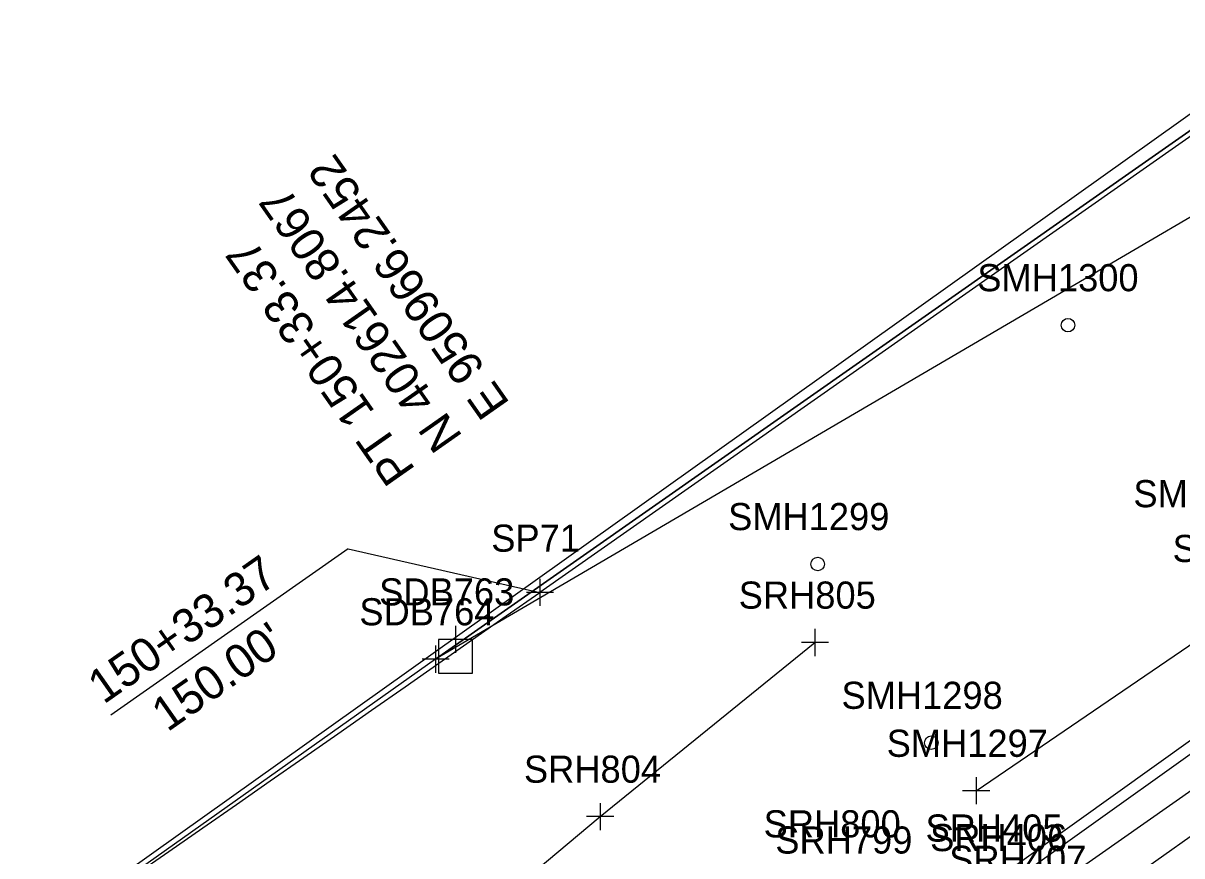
# Model space of a CAD drawing. Extents: x 941041 to 969446, y 397014 to 416764.
# Drawn here: x 950803.9 to 950974.8, y 402698.7 to 402821.6 of the extents above; entities that cross this region are included whole.
import ezdxf

# ---------------------------------------------------------------- set-up
doc = ezdxf.new("R2010")
doc.units = 0
for name, color, linetype in [('SURVEY - CENTERLINE - Preliminary Curve Text', 7, 'Continuous'), ('SURVEY - DRAINAGE - Area Shapes', 7, 'Continuous'), ('SURVEY - DTM - Breaklines', 7, 'Continuous'), ('SURVEY - DTM - Breaklines - Points - Locators', 7, 'Continuous'), ('SURVEY - DTM - Breaklines - Points - Numbers', 7, 'Continuous'), ('SURVEY - DTM - Spot Points - Locators', 7, 'Continuous'), ('SURVEY - DTM - Spot Points - Point Numbers', 7, 'Continuous'), ('SURVEY - DTM GRAPHICS - Boundary Line', 7, 'Continuous'), ('SURVEY - NON-TRANSPORTATION - Features', 7, 'Continuous'), ('SURVEY - NON-TRANSPORTATION - Features - Points - Locators', 7, 'Continuous'), ('SURVEY - NON-TRANSPORTATION - Features - Points - Numbers', 7, 'Continuous'), ('SURVEY - PROPERTY - ROW Lines', 7, 'Continuous'), ('SURVEY - PROPERTY - ROW Lines - Points - Locators', 7, 'Continuous'), ('SURVEY - PROPERTY - ROW Lines - Points - Numbers', 7, 'Continuous'), ('SURVEY - PROPERTY - ROW Markers - Points - Locators', 7, 'Continuous'), ('SURVEY - PROPERTY - ROW Markers - Points - Numbers', 7, 'Continuous'), ('SURVEY - PROPERTY - ROW Markers with Text', 7, 'Continuous'), ('SURVEY - PROPERTY - Station and Offset Flags', 7, 'Continuous'), ('SURVEY - TRANSPORTATION - Features', 7, 'Continuous'), ('SURVEY - TRANSPORTATION - Features - Points - Numbers', 7, 'Continuous'), ('SURVEY - TRANSPORTATION - Roads', 7, 'Continuous'), ('SURVEY - TRANSPORTATION - Roads - Points - Numbers', 7, 'Continuous'), ('SURVEY - VEGETATION - Features with Text', 7, 'Continuous')]:
    doc.layers.add(name, color=color, linetype=linetype)

msp = doc.modelspace()

# ---------------------------------------------------------------- linework, layer by layer
at = {"layer": 'SURVEY - DRAINAGE - Area Shapes'}
for points in [[(951570.1, 403333.86), (951394.91, 403299.54), (951364.56, 403085.05), (950690.3, 402604.57), (950747.14, 402539.76)], [(950765.73, 402528.11), (951145.6, 402792.15), (951242.57, 402873.52), (951348.31, 402952.21), (951398.95, 403004.27), (951428.85, 403040.93), (951473.12, 403113.97), (951570.1, 403333.86), (951394.91, 403299.54), (951364.56, 403085.05), (950690.3, 402604.57), (950747.14, 402539.76), (950765.73, 402528.11)]]:
    msp.add_lwpolyline(points, dxfattribs=at)
at = {"layer": 'SURVEY - DTM - Breaklines'}
for points in [[(951404.5, 403057.02), (951388.59, 403034.18), (951373.81, 403016.3), (951353.68, 402995.42), (951325.73, 402969.82), (951296.63, 402946.16), (951268.96, 402924.9), (951228.2, 402894.58), (951186.77, 402863.94), (951145.14, 402834.63), (951106.17, 402807.78), (951067.06, 402780.74), (951027.03, 402752.5), (950987.44, 402723.92), (950948.21, 402695.85), (950901.61, 402662.26), (950863.92, 402634.17), (950821.87, 402602.73), (950781, 402573.02)], [(950944.44, 402708.35), (950986.6, 402737.09)], [(950237.65, 402240.97), (950267.36, 402257.69), (950281.03, 402266.22), (950290.41, 402276.78), (950294.3, 402291.79), (950336.7, 402321.23), (950361.81, 402337.33), (950394.81, 402356.64), (950452.42, 402395.26), (950492.99, 402426.39), (950521.54, 402448.6), (950545.9, 402468.36), (950567.77, 402479.99), (950593.74, 402495.18), (950637.65, 402519.72), (950680.18, 402542.63), (950719.67, 402568.24), (950762.46, 402595.79), (950800.62, 402621.2), (950816.02, 402635.33), (950833.32, 402656.12), (950855.15, 402676.16), (950888.99, 402704.53), (950920.66, 402730.21)]]:
    msp.add_lwpolyline(points, dxfattribs=at)
at = {"layer": 'SURVEY - DTM - Breaklines - Points - Locators'}
for p, q in [((950920.66, 402732.21), (950920.66, 402728.21)), ((950922.66, 402730.21), (950918.66, 402730.21)), ((950944.44, 402710.35), (950944.44, 402706.35)), ((950946.44, 402708.35), (950942.44, 402708.35)), ((950888.99, 402706.53), (950888.99, 402702.53)), ((950890.99, 402704.53), (950886.99, 402704.53))]:
    msp.add_line(p, q, dxfattribs=at)
at = {"layer": 'SURVEY - DTM - Spot Points - Locators'}
for centre in [(950957.98, 402777.03), (950921.07, 402741.79), (950937.82, 402715.43)]:
    msp.add_circle(centre, 1, dxfattribs=at)
at = {"layer": 'SURVEY - DTM GRAPHICS - Boundary Line'}
msp.add_lwpolyline([(951405.32, 403106.55), (950864.72, 402727.75), (950737.53, 402637.64), (950693.7, 402607.67), (950660.44, 402585.43), (950616.59, 402556.18)], dxfattribs=at)
at = {"layer": 'SURVEY - NON-TRANSPORTATION - Features'}
msp.add_lwpolyline([(950864.72, 402727.75), (951405.32, 403106.55), (951490.75, 403254.61), (951622.56, 403452.94), (951851.46, 403680.18), (951878.49, 403682.56)], dxfattribs=at)
at = {"layer": 'SURVEY - NON-TRANSPORTATION - Features - Points - Locators'}
for p, q in [((950864.72, 402729.75), (950864.72, 402725.75)), ((950864.72, 402729.75), (950864.72, 402725.75)), ((950866.72, 402727.75), (950862.72, 402727.75)), ((950866.72, 402727.75), (950862.72, 402727.75))]:
    msp.add_line(p, q, dxfattribs=at)
at = {"layer": 'SURVEY - PROPERTY - ROW Lines'}
msp.add_line((951405.14, 403105.86), (950880.11, 402737.61), dxfattribs=at)
msp.add_arc((941043.59, 416761.87), 17130, 302.448118, 305.045557, dxfattribs=at)
at = {"layer": 'SURVEY - PROPERTY - ROW Lines - Points - Locators'}
for p, q in [((950880.11, 402739.61), (950880.11, 402735.61)), ((950880.11, 402739.61), (950880.11, 402735.61)), ((950882.11, 402737.61), (950878.11, 402737.61)), ((950882.11, 402737.61), (950878.11, 402737.61))]:
    msp.add_line(p, q, dxfattribs=at)
at = {"layer": 'SURVEY - PROPERTY - ROW Markers - Points - Locators'}
for p, q in [((950867.64, 402732.68), (950867.64, 402728.68)), ((950869.64, 402730.68), (950865.64, 402730.68))]:
    msp.add_line(p, q, dxfattribs=at)
at = {"layer": 'SURVEY - PROPERTY - ROW Markers with Text'}
msp.add_lwpolyline([(950867.64, 402730.68), (950865.14, 402730.68), (950865.14, 402725.68), (950870.14, 402725.68), (950870.14, 402730.68)], close=True, dxfattribs=at)
at = {"layer": 'SURVEY - PROPERTY - Station and Offset Flags'}
msp.add_line((950851.83, 402744.03), (950816.84, 402719.49), dxfattribs=at)
msp.add_lwpolyline([(950851.83, 402744.03), (950880.11, 402737.61)], dxfattribs=at)
at = {"layer": 'SURVEY - TRANSPORTATION - Features'}
msp.add_lwpolyline([(951406.86, 403056.25), (951390.68, 403032.37), (951376, 403015.34), (951355.22, 402994.23), (951327.1, 402968.39), (951298.08, 402944.15), (951270.44, 402922.46), (951229.64, 402892.03), (951187.14, 402861.33), (951146.52, 402833.1), (951107.71, 402806.53), (951068.28, 402778.93), (951028.06, 402751.02), (950988.38, 402722.54), (950949, 402694.44), (950902.92, 402661.08), (950864.64, 402632.92), (950822.64, 402601.73), (950781.7, 402572.06), (950745.88, 402544.94), (950716.67, 402522.96)], dxfattribs=at)
at = {"layer": 'SURVEY - TRANSPORTATION - Roads'}
for points in [[(951410.7, 403051.7), (951393.8, 403029.54), (951379.42, 403012.69), (951359.06, 402991.46), (951330.74, 402964.31), (951301.59, 402939.74), (951273.95, 402918.57), (951232.23, 402888.27), (951188.46, 402857.67), (951149.32, 402830.16), (951110.42, 402802.41), (951071.27, 402775.13), (951030.97, 402746.68), (950990.91, 402718.7), (950951.71, 402691.24), (950905.16, 402658.93), (950866.67, 402631.07), (950824.58, 402600.25), (950783.31, 402570.16)], [(951414.76, 403048.91), (951397.41, 403026.54), (951382.84, 403009.48), (951362.61, 402987.81), (951333.74, 402960.2), (951304.6, 402935.06), (951276.51, 402913.06), (951235.4, 402883.45), (951192.72, 402853.54), (951151.98, 402824.99), (951113.28, 402797.96), (951074.6, 402770.69), (951034.02, 402742.32), (950993.7, 402714.11), (950954.4, 402686.24), (950909.08, 402652.74), (950870.89, 402623.6), (950829.23, 402591.97), (950787.49, 402560.18)]]:
    msp.add_lwpolyline(points, dxfattribs=at)
at = {"layer": 'SURVEY - VEGETATION - Features with Text'}
msp.add_lwpolyline([(951868.69, 403693.52), (951860.48, 403665.55), (951848.34, 403659.79), (951791.64, 403612.32), (951746.84, 403559.94), (951643.65, 403453.43), (951600.78, 403415.7), (951529.23, 403307.04), (951432.31, 403122.21), (951397.48, 403082.19), (951387.06, 403063.16), (951343.99, 403026.97), (951317.91, 403024.99), (951275.96, 402980.18), (951202.21, 402921.55), (951122.62, 402900.03), (951100.62, 402857.44), (951081.13, 402854.56), (950864.72, 402727.75), (951405.32, 403106.55), (951588.18, 403418.84), (951738.55, 403643.48), (951840.77, 403717.4), (951868.69, 403693.52)], dxfattribs=at)

# ---------------------------------------------------------------- texts
at = {"layer": 'SURVEY - CENTERLINE - Preliminary Curve Text'}
for s, p in [('E 950966.2452', (950875.77, 402765.46)), ('N 402614.8067', (950868.81, 402760.58)), ('PT 150+33.37', (950861.85, 402755.7))]:
    msp.add_text(s, height=5, rotation=125.0456, dxfattribs=at).set_placement(p)
at = {"layer": 'SURVEY - DTM - Breaklines - Points - Numbers'}
for s, p in [('SMH1302', (950973.41, 402742.09)), ('SRH805', (950909.42, 402735.21)), ('SMH1297', (950931.24, 402713.35)), ('SRH804', (950877.75, 402709.53)), ('SRH800', (950913.1, 402701.47)), ('SRH405', (950936.97, 402700.85)), ('SRH799', (950914.82, 402699.08))]:
    msp.add_text(s, height=4, dxfattribs=at).set_placement(p)
at = {"layer": 'SURVEY - DTM - Spot Points - Point Numbers'}
for s, p in [('SMH1300', (950944.61, 402782.03)), ('SMH1301', (950967.63, 402750.17)), ('SMH1299', (950907.86, 402746.79)), ('SMH1298', (950924.58, 402720.43))]:
    msp.add_text(s, height=4, dxfattribs=at).set_placement(p)
at = {"layer": 'SURVEY - NON-TRANSPORTATION - Features - Points - Numbers'}
msp.add_text('SDB764', height=4, dxfattribs=at).set_placement((950853.48, 402732.75))
msp.add_text('SDB764', height=4, dxfattribs=at).set_placement((950853.48, 402732.75))
at = {"layer": 'SURVEY - PROPERTY - ROW Lines - Points - Numbers'}
msp.add_text('SP71', height=4, dxfattribs=at).set_placement((950872.93, 402743.61))
at = {"layer": 'SURVEY - PROPERTY - ROW Markers - Points - Numbers'}
msp.add_text('SDB763', height=4, dxfattribs=at).set_placement((950856.4, 402735.68))
at = {"layer": 'SURVEY - PROPERTY - Station and Offset Flags'}
for s, p in [('150+33.37', (950815.76, 402721.02)), ("150.00'", (950825.17, 402716.93))]:
    msp.add_text(s, height=5, rotation=35.0456, dxfattribs=at).set_placement(p)
at = {"layer": 'SURVEY - TRANSPORTATION - Features - Points - Numbers'}
msp.add_text('SRH406', height=4, dxfattribs=at).set_placement((950937.65, 402699.44))
at = {"layer": 'SURVEY - TRANSPORTATION - Roads - Points - Numbers'}
msp.add_text('SRH407', height=4, dxfattribs=at).set_placement((950940.47, 402696.24))

doc.saveas('drawing.dxf')
